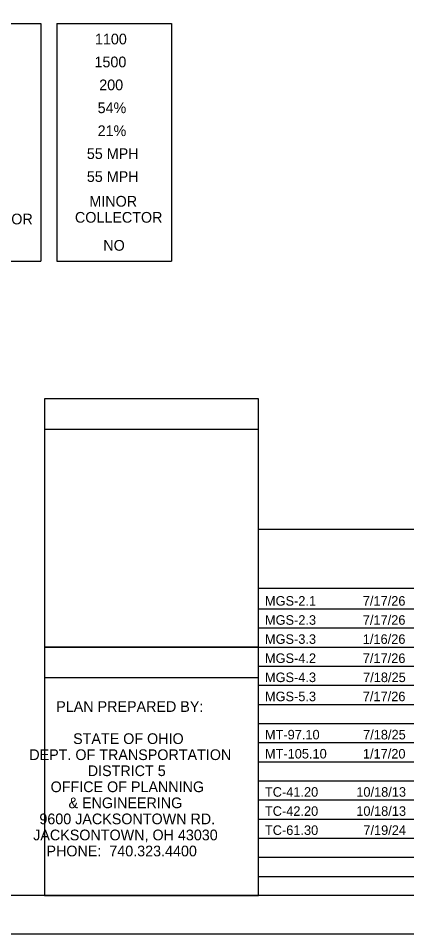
# Model space of a CAD drawing. Extents: x 0 to 34, y 0 to 22.
# Drawn here: x 7.01 to 12.09, y 0 to 11.98 of the extents above; entities that cross this region are included whole.
import ezdxf

# ---------------------------------------------------------------- set-up
doc = ezdxf.new("R2010")
doc.units = 0
for name, color, linetype in [('Default', 7, 'Continuous'), ('SH_Border', 7, 'Continuous'), ('SH_Cut_Line', 7, 'Continuous'), ('SH_Data', 7, 'Continuous'), ('SH_Text', 7, 'Continuous')]:
    doc.layers.add(name, color=color, linetype=linetype)

msp = doc.modelspace()

# ---------------------------------------------------------------- linework, layer by layer
at = {"layer": 'Default'}
for p, q in [((5.799, 11.91), (7.299, 11.91)), ((7.299, 11.91), (7.299, 8.8)), ((7.509, 11.91), (9.009, 11.91)), ((7.509, 11.91), (7.509, 8.8)), ((9.009, 11.91), (9.009, 8.8)), ((5.799, 8.8), (7.299, 8.8)), ((7.509, 8.8), (9.009, 8.8))]:
    msp.add_line(p, q, dxfattribs=at)
at = {"layer": 'SH_Border'}
msp.add_lwpolyline([(1.5, 21.5), (33.5, 21.5), (33.5, 0.5), (1.5, 0.5)], close=True, dxfattribs=at)
at = {"layer": 'SH_Cut_Line'}
msp.add_lwpolyline([(0, 0), (34, 0), (34, 22), (0, 22)], close=True, dxfattribs=at)
at = {"layer": 'SH_Data'}
for p, q in [((7.35, 6.6), (10.15, 6.6)), ((10.15, 5.292), (23.6, 5.292)), ((10.15, 0.5), (10.15, 5.292)), ((10.15, 4.521), (23.6, 4.521)), ((10.15, 4.25), (23.6, 4.25)), ((10.15, 4), (23.6, 4)), ((10.15, 3.75), (23.6, 3.75)), ((10.15, 3.5), (23.6, 3.5)), ((7.35, 3.35), (10.15, 3.35)), ((10.15, 3.25), (23.6, 3.25)), ((10.15, 3), (23.6, 3)), ((10.15, 2.75), (23.6, 2.75)), ((10.15, 2.5), (23.6, 2.5)), ((10.15, 2.25), (23.6, 2.25)), ((10.15, 2), (23.6, 2)), ((10.15, 1.75), (23.6, 1.75)), ((10.15, 1.5), (23.6, 1.5)), ((10.15, 1.25), (23.6, 1.25)), ((10.15, 1), (23.6, 1)), ((10.15, 0.75), (23.6, 0.75))]:
    msp.add_line(p, q, dxfattribs=at)
for points in [[(10.15, 7), (7.35, 7), (7.35, 3.75), (10.15, 3.75)], [(10.15, 3.75), (7.35, 3.75), (7.35, 0.5), (10.15, 0.5)]]:
    msp.add_lwpolyline(points, close=True, dxfattribs=at)

# ---------------------------------------------------------------- texts
at = {"layer": 'Default'}
for s, p in [('MGS-2.1', (10.232, 4.292)), ('7/17/26', (11.512, 4.292)), ('MGS-2.3', (10.232, 4.042)), ('7/17/26', (11.512, 4.042)), ('MGS-3.3', (10.232, 3.792)), ('1/16/26', (11.512, 3.792)), ('MGS-4.2', (10.232, 3.542)), ('7/17/26', (11.512, 3.542)), ('MGS-4.3', (10.232, 3.292)), ('7/18/25', (11.516, 3.292)), ('MGS-5.3', (10.232, 3.042)), ('7/17/26', (11.512, 3.042)), ('MT-97.10', (10.232, 2.542)), ('7/18/25', (11.516, 2.542)), ('MT-105.10', (10.232, 2.292)), ('1/17/20', (11.513, 2.292)), ('TC-41.20', (10.232, 1.792)), ('10/18/13', (11.427, 1.792)), ('TC-42.20', (10.232, 1.542)), ('10/18/13', (11.427, 1.542)), ('TC-61.30', (10.232, 1.292)), ('7/19/24', (11.519, 1.292))]:
    msp.add_text(s, height=0.125, dxfattribs=at).set_placement(p)
at = {"layer": 'SH_Text'}
for s, p in [('1100', (8.009, 11.636)), ('1500', (8.003, 11.336)), ('200', (8.065, 11.036)), ('54%', (8.044, 10.736)), ('21%', (8.044, 10.436)), ('55 MPH', (7.903, 10.136)), ('55 MPH', (7.903, 9.836)), ('MINOR', (7.936, 9.513)), ('COLLECTOR', (6.051, 9.281)), ('COLLECTOR', (7.747, 9.303)), ('NO', (8.118, 8.936)), ('PLAN PREPARED BY:', (7.502, 2.902)), ('STATE OF OHIO', (7.723, 2.482)), ('DEPT. OF TRANSPORTATION', (7.15, 2.272)), ('DISTRICT 5', (7.915, 2.062)), ('OFFICE OF PLANNING', (7.429, 1.852)), ('& ENGINEERING', (7.663, 1.642)), ('9600 JACKSONTOWN RD.', (7.282, 1.432)), ('JACKSONTOWN, OH 43030', (7.201, 1.222)), ('PHONE:  740.323.4400', (7.375, 1.012))]:
    msp.add_text(s, height=0.14, dxfattribs=at).set_placement(p)

doc.saveas('drawing.dxf')
